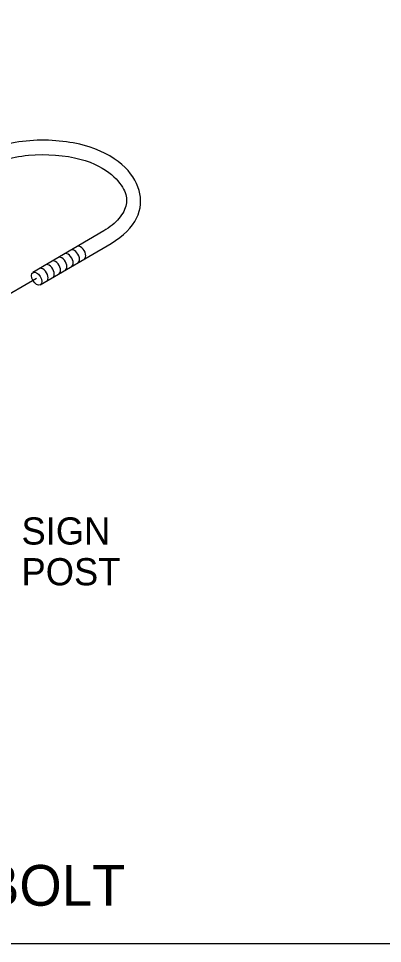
# Model space of a CAD drawing. Extents: x 99862 to 103151, y 100000 to 105076.
# Drawn here: x 101398 to 101613, y 100000 to 100544 of the extents above; entities that cross this region are included whole.
import ezdxf

# ---------------------------------------------------------------- set-up
doc = ezdxf.new("R2010")
doc.units = 0
for name, color, linetype in [('Level 1', 7, 'Continuous'), ('Level 12', 7, 'Continuous'), ('Level 16', 7, 'Continuous'), ('Level 20', 7, 'Continuous')]:
    doc.layers.add(name, color=color, linetype=linetype)

msp = doc.modelspace()

# ---------------------------------------------------------------- linework, layer by layer
at = {"layer": 'Level 1'}
msp.add_lwpolyline([(99862, 99999.5), (103151, 99999.5), (103151, 102075.5), (99862, 102075.5)], close=True, dxfattribs=at)
at = {"layer": 'Level 12'}
for p, q in [((101448.47, 100419.09), (101406.83, 100394.69)), ((101411.1, 100387.34), (101452.77, 100411.76))]:
    msp.add_line(p, q, dxfattribs=at)
for centre, major_axis, ratio, start_param, end_param in [((101446.06, 100412.75), (2.13, -3.68), 0.57735, 3.133556, 3.157063), ((101450.62, 100415.43), (2.15, -3.67), 0.581626, 3.13818, 3.141605), ((101434.93, 100406.23), (2.13, -3.68), 0.57735, 0.003717, 3.155143), ((101427.51, 100401.88), (2.13, -3.68), 0.57735, 0.003717, 3.15362), ((101431.22, 100404.06), (2.13, -3.68), 0.57735, 0.003717, 3.154413), ((101416.38, 100395.36), (2.13, -3.68), 0.57735, 0.003717, 3.150566), ((101420.09, 100397.54), (2.13, -3.68), 0.57735, 0.003717, 3.151747), ((101423.8, 100399.71), (2.13, -3.68), 0.57735, 0.003717, 3.152743), ((101412.68, 100393.19), (2.13, -3.68), 0.57735, 0.003717, 3.149026)]:
    msp.add_ellipse(centre, major_axis=major_axis, ratio=ratio, start_param=start_param, end_param=end_param, dxfattribs=at)
msp.add_ellipse((101408.97, 100391.02), major_axis=(2.13, -3.68), ratio=0.57735, dxfattribs=at)
for points in [[(101452.77, 100411.76), (101460.2, 100416.12), (101470.27, 100426.38), (101471.04, 100443.15), (101461.3, 100458.77), (101438.63, 100471.21), (101402.15, 100474.14), (101380.45, 100467.66), (101372.14, 100462.86)], [(101376.39, 100455.5), (101383.61, 100459.67), (101403.53, 100465.61), (101437.16, 100462.63), (101454.85, 100452.2), (101461.58, 100442.22), (101462.65, 100434.97), (101458.24, 100426.24), (101452.08, 100421.19), (101448.47, 100419.09)]]:
    msp.add_open_spline(points, degree=3, dxfattribs=at)
at = {"layer": 'Level 16'}
msp.add_line((101408.97, 100391.02), (101254.27, 100301.55), dxfattribs=at)

# ---------------------------------------------------------------- texts
at = {"layer": 'Level 20'}
for s, p in [('SIGN', (101400.06, 100234.41)), ('POST', (101400.06, 100210.41))]:
    msp.add_text(s, height=16, rotation=360, dxfattribs=at).set_placement(p)
msp.add_text('PIPE CLAMP AND U-BOLT', height=24, dxfattribs=at).set_placement((101065.31, 100021.74))

doc.saveas('drawing.dxf')
